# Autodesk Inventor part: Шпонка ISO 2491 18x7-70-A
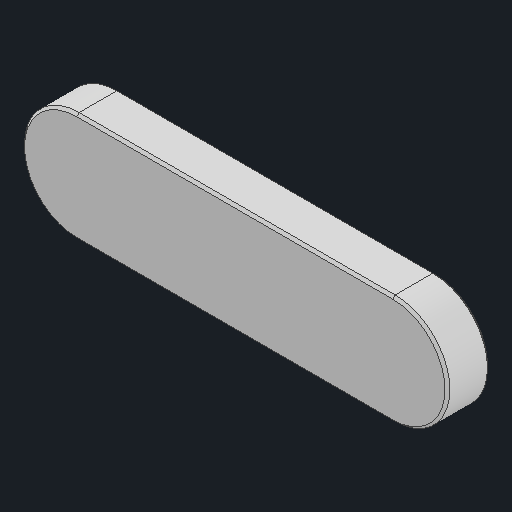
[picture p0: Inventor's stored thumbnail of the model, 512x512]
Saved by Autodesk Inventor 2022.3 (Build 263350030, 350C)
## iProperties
Created: 2020-09
Part Number: Шпонка ISO 2491 18x7-70-A
Material: Типовые
Document SubType Name: Modeling
Designer: Карташов
Density: 1 g/cm^3
Appearance: По умолчанию
Title: D:\мои документы\Ирина\_WorldSkills\2020_09 ФНЧ\Module A\Участникам\GIVEN\Шпонка ISO 2491 18x7-70-A.stp
Author: Дом
Sending System: Autodesk Inventor 2021
Preprocessor: ST-DEVELOPER v18.1
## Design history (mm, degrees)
feature "Твердое тело2"
node "Твердое тело1"
